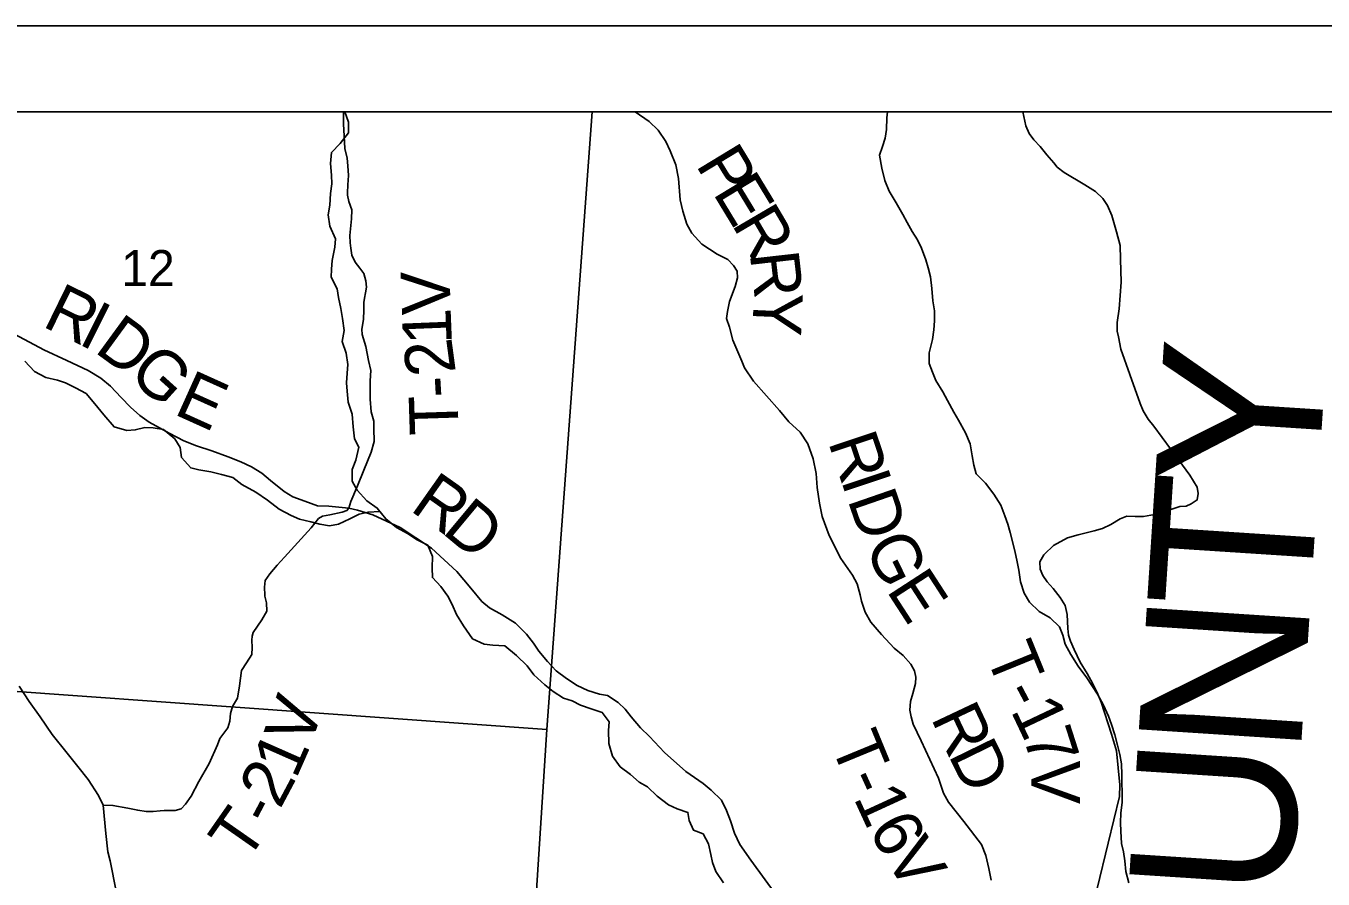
# Model space of a CAD drawing. Extents: x -13.7 to 34, y 0 to 32.3.
# Drawn here: x 24.332 to 25.84, y 20.009 to 21 of the extents above; entities that cross this region are included whole.
import ezdxf

# ---------------------------------------------------------------- set-up
doc = ezdxf.new("R2010")
doc.units = 0
for name, color, linetype in [('GM_X_Corporation', 7, 'Continuous'), ('GM_X_County_Road', 7, 'Continuous'), ('GM_X_County_Road_Text', 7, 'Continuous'), ('GM_X_County_Text', 7, 'Continuous'), ('GM_X_Minor_River', 7, 'Continuous'), ('GM_X_Section_Text', 7, 'Continuous'), ('GM_X_Township_Road', 7, 'Continuous'), ('GM_X_Township_Road_Text', 7, 'Continuous'), ('SH_Data', 7, 'Continuous')]:
    doc.layers.add(name, color=color, linetype=linetype)

msp = doc.modelspace()

# ---------------------------------------------------------------- linework, layer by layer
at = {"layer": 'GM_X_Corporation'}
for points in [[(26.0026, 20.9), (23.5167, 20.9), (23.5167, 14.1)], [(26.0026, 20.9), (23.5167, 20.9), (23.5167, 15.1495)]]:
    msp.add_lwpolyline(points, dxfattribs=at)
for points in [[(24.9905, 20.9), (23.9809, 20.9), (23.9438, 20.2537), (24.938, 20.1823)], [(23.9438, 20.2537), (24.938, 20.1823), (24.8727, 19.1684), (23.8661, 19.2385)]]:
    msp.add_lwpolyline(points, close=True, dxfattribs=at)
at = {"layer": 'GM_X_County_Road'}
msp.add_lwpolyline([(25.2051, 19.9891), (25.175, 20.0305), (25.1622, 20.0486), (25.1561, 20.0621), (25.1513, 20.0761), (25.1467, 20.0883), (25.1411, 20.1004), (25.1291, 20.1121), (25.1196, 20.1195), (25.0994, 20.1335), (25.0745, 20.1557), (25.0571, 20.1743), (25.0467, 20.1845), (25.036, 20.1971), (25.0288, 20.2062), (25.0208, 20.2139), (25.0084, 20.222), (24.9992, 20.2236), (24.9857, 20.2276), (24.9731, 20.2335), (24.9607, 20.2415), (24.9489, 20.2506), (24.9387, 20.2614), (24.9288, 20.2733), (24.9224, 20.2828), (24.9142, 20.2932), (24.9015, 20.3058), (24.8861, 20.3155), (24.8711, 20.3238), (24.8624, 20.3313), (24.8494, 20.3466), (24.8334, 20.366), (24.804, 20.3932), (24.7675, 20.417), (24.7357, 20.4317), (24.7178, 20.4373), (24.7077, 20.4397), (24.6846, 20.4418), (24.6712, 20.4422), (24.6568, 20.4476), (24.6428, 20.4529), (24.6325, 20.459), (24.6167, 20.4716), (24.6067, 20.4801), (24.5947, 20.4878), (24.5822, 20.4936), (24.5676, 20.4994), (24.5487, 20.5063), (24.5306, 20.5119), (24.516, 20.5177), (24.4991, 20.5266), (24.4879, 20.533), (24.4759, 20.5395), (24.465, 20.5473), (24.4539, 20.557), (24.443, 20.5682), (24.4306, 20.5813), (24.4196, 20.5908), (24.4048, 20.5995), (24.3801, 20.6113), (24.3534, 20.6236), (24.3191, 20.642)], dxfattribs=at)
at = {"layer": 'GM_X_Minor_River'}
for points in [[(24.7161, 20.4954), (24.7195, 20.5105), (24.7145, 20.52), (24.713, 20.534), (24.7115, 20.5488), (24.7069, 20.5628), (24.7058, 20.5757), (24.705, 20.5852), (24.7057, 20.5966), (24.7065, 20.6064), (24.7046, 20.6197), (24.7, 20.6333), (24.7023, 20.6462), (24.7004, 20.6599), (24.6984, 20.6716), (24.6958, 20.6845), (24.6943, 20.6944), (24.6874, 20.708), (24.6878, 20.7175), (24.6885, 20.7273), (24.6915, 20.7429), (24.6923, 20.7528), (24.6858, 20.7675), (24.6839, 20.7804), (24.6858, 20.7918), (24.6865, 20.8051), (24.688, 20.8164), (24.6877, 20.8267), (24.6865, 20.84), (24.6876, 20.8528), (24.6978, 20.8635), (24.7073, 20.8756), (24.7073, 20.8881), (24.7032, 20.9)], [(25.6144, 20.0042), (25.611, 20.0174), (25.6098, 20.0296), (25.6083, 20.0402), (25.606, 20.05), (25.6049, 20.0641), (25.6045, 20.0739), (25.6052, 20.0857), (25.6067, 20.0974), (25.6067, 20.1099), (25.6063, 20.1202), (25.6063, 20.1296), (25.6059, 20.1425), (25.604, 20.1535), (25.6013, 20.1641), (25.5979, 20.1763), (25.5941, 20.1884), (25.5907, 20.1979), (25.585, 20.2108), (25.5778, 20.2236), (25.5656, 20.2426), (25.5554, 20.2562), (25.5471, 20.2695), (25.5402, 20.2816), (25.5376, 20.2922), (25.5338, 20.3017), (25.5231, 20.3123), (25.5102, 20.3195), (25.4989, 20.3304), (25.4928, 20.3407), (25.4886, 20.3539), (25.4867, 20.3676), (25.4844, 20.3774), (25.4818, 20.3899), (25.4764, 20.4112), (25.4738, 20.421), (25.4703, 20.4309), (25.4654, 20.443), (25.4574, 20.4559), (25.4476, 20.4687), (25.437, 20.4797), (25.4343, 20.4896), (25.4324, 20.5006), (25.4301, 20.5142), (25.4244, 20.5271), (25.4164, 20.5419), (25.4111, 20.5513), (25.4035, 20.5646), (25.3982, 20.5748), (25.3902, 20.5881), (25.3861, 20.5976), (25.3823, 20.6078), (25.3822, 20.6203), (25.386, 20.6355), (25.3879, 20.6468), (25.3883, 20.6575), (25.3886, 20.6688), (25.3867, 20.6806), (25.3852, 20.695), (25.384, 20.7083), (25.381, 20.7189), (25.3783, 20.7283), (25.3734, 20.7416), (25.3688, 20.7515), (25.3627, 20.7613), (25.3567, 20.7715), (25.3517, 20.781), (25.3441, 20.7943), (25.3358, 20.8079), (25.3309, 20.8204), (25.3274, 20.8348), (25.3244, 20.85), (25.3282, 20.8598), (25.3312, 20.8697), (25.3327, 20.8796), (25.333, 20.8932), (25.3339, 20.9)], [(24.7439, 20.4357), (24.7302, 20.4351), (24.7199, 20.4328), (24.709, 20.4271), (24.6957, 20.421), (24.6855, 20.4191), (24.6741, 20.421), (24.6635, 20.4236), (24.6506, 20.427), (24.6408, 20.4312), (24.6268, 20.4384), (24.6131, 20.449), (24.5995, 20.4584), (24.5835, 20.4671), (24.5729, 20.4751), (24.5597, 20.4788), (24.5475, 20.4818), (24.5335, 20.4841), (24.524, 20.4864), (24.5134, 20.4985), (24.5119, 20.5102), (24.5054, 20.5201), (24.4922, 20.5311), (24.4804, 20.5329), (24.4706, 20.5333), (24.4596, 20.5306), (24.4497, 20.5299), (24.435, 20.534), (24.4232, 20.548), (24.4126, 20.5609), (24.4023, 20.573), (24.3902, 20.5794), (24.3785, 20.5851), (24.369, 20.5885), (24.3557, 20.5915), (24.3425, 20.5983), (24.3311, 20.6104)], [(25.1432, 20.0043), (25.1345, 20.0175), (25.1303, 20.0278), (25.1284, 20.0372), (25.1257, 20.0494), (25.1196, 20.0611), (25.1083, 20.0656), (25.1033, 20.0766), (25.1018, 20.0861), (25.0893, 20.0902), (25.0794, 20.0948), (25.0662, 20.105), (25.0548, 20.1156), (25.0453, 20.1213), (25.0351, 20.13), (25.023, 20.1391), (25.0142, 20.1516), (25.01, 20.166), (25.0096, 20.1811), (25.0104, 20.1914), (25.0024, 20.202), (24.9895, 20.2065), (24.977, 20.2106), (24.9672, 20.2156), (24.9573, 20.219), (24.9452, 20.2265), (24.9357, 20.2345), (24.9228, 20.2458), (24.9152, 20.2564), (24.9027, 20.2685), (24.8891, 20.2795), (24.8751, 20.2803), (24.8652, 20.2814), (24.8516, 20.2878), (24.8409, 20.303), (24.833, 20.3162), (24.828, 20.3276), (24.8227, 20.3374), (24.8147, 20.3484), (24.8049, 20.359), (24.8045, 20.3704), (24.8049, 20.3833), (24.7995, 20.3965), (24.7866, 20.4033), (24.7768, 20.4098), (24.7631, 20.417), (24.7506, 20.4272), (24.7408, 20.4397), (24.7286, 20.448), (24.7176, 20.4605), (24.7116, 20.4711), (24.7116, 20.4844), (24.7161, 20.4954)]]:
    msp.add_lwpolyline(points, dxfattribs=at)
at = {"layer": 'GM_X_Township_Road'}
for points in [[(24.7063, 20.8059), (24.7067, 20.8153), (24.7073, 20.8262), (24.7068, 20.8373), (24.706, 20.8462), (24.7033, 20.8574), (24.7017, 20.8863), (24.7015, 20.9)], [(25.4545, 20.0075), (25.4517, 20.0207), (25.4482, 20.0361), (25.4433, 20.0486), (25.4224, 20.0754), (25.4046, 20.098), (25.399, 20.1086), (25.393, 20.1259), (25.373, 20.1693), (25.3638, 20.1886), (25.3612, 20.197), (25.3597, 20.205), (25.3607, 20.2149), (25.3635, 20.2243), (25.3665, 20.2358), (25.3668, 20.2432), (25.3653, 20.2504), (25.361, 20.2585), (25.352, 20.2685), (25.3416, 20.2769), (25.3267, 20.2927), (25.3145, 20.307), (25.3079, 20.3188), (25.3038, 20.3315), (25.302, 20.3389), (25.2985, 20.3516), (25.2931, 20.3619), (25.2795, 20.381), (25.266, 20.4078), (25.2581, 20.43), (25.2548, 20.4453), (25.2523, 20.4637), (25.251, 20.48), (25.2474, 20.497), (25.2413, 20.5144), (25.2323, 20.528), (25.2193, 20.5399), (25.2082, 20.553), (25.178, 20.5871), (25.1678, 20.6026), (25.1647, 20.6103), (25.154, 20.6348), (25.1502, 20.6499), (25.1469, 20.6599), (25.1479, 20.668), (25.1504, 20.6797), (25.1569, 20.6974), (25.1594, 20.7073), (25.1591, 20.7149), (25.155, 20.7218), (25.1481, 20.7284), (25.1359, 20.7349), (25.118, 20.7466), (25.1066, 20.7593), (25.1005, 20.7695), (25.0958, 20.7848), (25.093, 20.7978), (25.091, 20.8228), (25.0879, 20.8386), (25.0814, 20.8548), (25.0763, 20.8657), (25.0673, 20.8787), (25.0569, 20.8889), (25.0404, 20.9)], [(25.5162, 20.3861), (25.5267, 20.3963), (25.5431, 20.4052), (25.5556, 20.4088), (25.5742, 20.4134), (25.5836, 20.416), (25.5936, 20.4208), (25.6041, 20.4274), (25.6119, 20.4302), (25.6216, 20.4299), (25.6314, 20.43), (25.6443, 20.4323), (25.6577, 20.4363), (25.6622, 20.4376), (25.6665, 20.4391), (25.6735, 20.4414), (25.6809, 20.4419), (25.6869, 20.4445), (25.6938, 20.4493), (25.6951, 20.4567), (25.6936, 20.4642), (25.6852, 20.4779), (25.6627, 20.5085), (25.6433, 20.5351), (25.637, 20.5432), (25.6309, 20.5529), (25.6275, 20.5611), (25.6156, 20.5951), (25.6049, 20.6244), (25.6022, 20.6389), (25.6008, 20.6455), (25.6007, 20.6555), (25.6033, 20.6713), (25.6056, 20.7022), (25.6046, 20.729), (25.6041, 20.7447), (25.6002, 20.7606), (25.5946, 20.7797), (25.5897, 20.7915), (25.5842, 20.7994), (25.5755, 20.8078), (25.5633, 20.8155), (25.5393, 20.8297), (25.5311, 20.836), (25.527, 20.841), (25.5189, 20.8501), (25.5115, 20.8599), (25.504, 20.8677), (25.4984, 20.8749), (25.4948, 20.8841), (25.4911, 20.9)], [(24.7077, 20.4397), (24.7102, 20.4472), (24.718, 20.4655), (24.7251, 20.4839), (24.7339, 20.5048), (24.7373, 20.5169), (24.7369, 20.5323), (24.7368, 20.5408), (24.7336, 20.5514), (24.7326, 20.5662), (24.7326, 20.5874), (24.7332, 20.5997), (24.7306, 20.6112), (24.7274, 20.6275), (24.7232, 20.6413), (24.7227, 20.6476), (24.7248, 20.6588), (24.7251, 20.6702), (24.7251, 20.6788), (24.7259, 20.6837), (24.7271, 20.6898), (24.7285, 20.6963), (24.7277, 20.7039), (24.7254, 20.7123), (24.7204, 20.7186), (24.7153, 20.7256), (24.7112, 20.7338), (24.7102, 20.7417), (24.7093, 20.7479), (24.709, 20.7565), (24.7109, 20.776), (24.7112, 20.7864), (24.7078, 20.7961), (24.7062, 20.8035), (24.7063, 20.8059)], [(24.6103, 20.3373), (24.6101, 20.3384), (24.6096, 20.348), (24.6104, 20.3555), (24.616, 20.3634), (24.6245, 20.3733), (24.6331, 20.3828), (24.6641, 20.4169), (24.6726, 20.4276), (24.6772, 20.4304), (24.6856, 20.4318), (24.7002, 20.4351), (24.7056, 20.4368), (24.7077, 20.4397)], [(25.5777, 19.9976), (25.5903, 20.0503), (25.6035, 20.1045), (25.6038, 20.1182), (25.6, 20.1575), (25.5944, 20.1769), (25.5821, 20.2141), (25.5785, 20.2233), (25.5727, 20.2353), (25.5661, 20.2473), (25.5578, 20.2605), (25.551, 20.2753), (25.5466, 20.2851), (25.5443, 20.292), (25.5434, 20.2999), (25.5425, 20.3159), (25.5403, 20.3266), (25.5344, 20.3358), (25.5263, 20.3461), (25.5193, 20.3539), (25.5145, 20.3613), (25.5115, 20.3688), (25.511, 20.3771), (25.5155, 20.3853), (25.5162, 20.3861)], [(24.4221, 20.0945), (24.4336, 20.0942), (24.4509, 20.0909), (24.4625, 20.0886), (24.4722, 20.0873), (24.4803, 20.0873), (24.4885, 20.0879), (24.4931, 20.0881), (24.4991, 20.0884), (24.5058, 20.0883), (24.5129, 20.0901), (24.5178, 20.0958), (24.5244, 20.105), (24.5333, 20.1221), (24.5456, 20.143), (24.5553, 20.1647), (24.5578, 20.1718), (24.5671, 20.1843), (24.5693, 20.1922), (24.5701, 20.2009), (24.5727, 20.209), (24.5782, 20.2188), (24.5806, 20.2333), (24.5829, 20.2509), (24.589, 20.2598), (24.5951, 20.2697), (24.5956, 20.2777), (24.5951, 20.2861), (24.5954, 20.2907), (24.5964, 20.2952), (24.6066, 20.3098), (24.6124, 20.3198), (24.6119, 20.3295), (24.6103, 20.3373)], [(24.4477, 19.8466), (24.4473, 19.8494), (24.4469, 19.857), (24.4519, 19.8996), (24.4519, 19.9146), (24.4468, 19.9577), (24.4418, 19.9782), (24.4372, 19.9945), (24.4305, 20.0299), (24.4277, 20.0401), (24.4255, 20.0614), (24.4221, 20.0945), (24.417, 20.1059), (24.405, 20.1244), (24.3929, 20.1395), (24.3803, 20.1551), (24.3629, 20.1767), (24.3489, 20.1972), (24.3363, 20.215), (24.3245, 20.2327)]]:
    msp.add_lwpolyline(points, dxfattribs=at)
at = {"layer": 'SH_Data'}
for points in [[(23.4167, 21), (30.4167, 21), (30.4167, 14), (23.4167, 14)], [(23.5167, 20.9), (30.3167, 20.9), (30.3167, 14.1), (23.5167, 14.1)]]:
    msp.add_lwpolyline(points, close=True, dxfattribs=at)

# ---------------------------------------------------------------- texts
at = {"layer": 'GM_X_County_Road_Text'}
for s, rotation, p in [('R', 333.9621, (24.35, 20.6516)), ('I', 333.3721, (24.3918, 20.6312)), ('D', 323.8572, (24.4106, 20.622)), ('G', 317.9299, (24.4497, 20.5935)), ('E', 335.7341, (24.5029, 20.5495)), ('R', 324.8603, (24.7775, 20.4377)), ('D', 320.2439, (24.8147, 20.4116))]:
    msp.add_text(s, height=0.0568, rotation=rotation, dxfattribs=at).set_placement(p)
at = {"layer": 'GM_X_County_Text'}
for s, rotation, p in [('Y', 86.2856, (25.8337, 20.4582)), ('T', 86.285, (25.8245, 20.3168)), ('N', 86.285, (25.8137, 20.1496)), ('U', 86.2853, (25.8028, 19.9825))]:
    msp.add_text(s, height=0.1894, rotation=rotation, dxfattribs=at).set_placement(p)
at = {"layer": 'GM_X_Section_Text'}
msp.add_text('12', height=0.04186, rotation=0, dxfattribs=at).set_placement((24.4432, 20.6977))
at = {"layer": 'GM_X_Township_Road_Text'}
for s, rotation, p in [('P', 301.2751, (25.1102, 20.8389)), ('E', 301.2717, (25.1301, 20.8062)), ('R', 300.3888, (25.152, 20.77)), ('R', 276.4458, (25.1737, 20.7357)), ('V', 91.9675, (24.8264, 20.6655)), ('Y', 267.5076, (25.1788, 20.6917)), ('1', 92.2904, (24.8277, 20.6306)), ('2', 97.6572, (24.8323, 20.5973)), ('-', 93.2943, (24.8341, 20.5694)), ('T', 91.8346, (24.8355, 20.5253)), ('R', 288.5325, (25.2645, 20.5168)), ('I', 288.5317, (25.2794, 20.4725)), ('D', 289.0989, (25.287, 20.4498)), ('G', 295.9401, (25.3062, 20.3957)), ('E', 302.9715, (25.3318, 20.3442)), ('T', 292.1372, (25.4472, 20.2698)), ('-', 297.9278, (25.4659, 20.2248)), ('V', 70.361, (24.662, 20.1601)), ('1', 295.385, (25.4765, 20.2047)), ('R', 295.2838, (25.3837, 20.196)), ('7', 287.8014, (25.4908, 20.175)), ('T', 292.3776, (25.267, 20.166)), ('D', 296.0196, (25.404, 20.1531)), ('1', 66.1704, (24.6462, 20.1238)), ('2', 61.971, (24.6277, 20.0889)), ('V', 270.1239, (25.5008, 20.1462)), ('-', 294.4616, (25.2841, 20.1247)), ('1', 294.6608, (25.2939, 20.1032)), ('-', 62.2182, (24.6169, 20.0683)), ('T', 55.0761, (24.5885, 20.0268)), ('6', 299.606, (25.3109, 20.0667)), ('V', 302.2015, (25.3296, 20.0338))]:
    msp.add_text(s, height=0.0568, rotation=rotation, dxfattribs=at).set_placement(p)

doc.saveas('drawing.dxf')
